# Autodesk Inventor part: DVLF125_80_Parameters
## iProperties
Created: 2010-04
Part Number: DVLF125_80_Parameters
Document SubType Name: Modeling
Designer: TB
Density: 1 g/cm^3
Slaglengde: 100.000 mm
Vinkel_Plussport: 0.00 deg
Vinkel_Minusport: 0.00 deg
Forlengelse_rør: 0.000 mm
Author: TB
